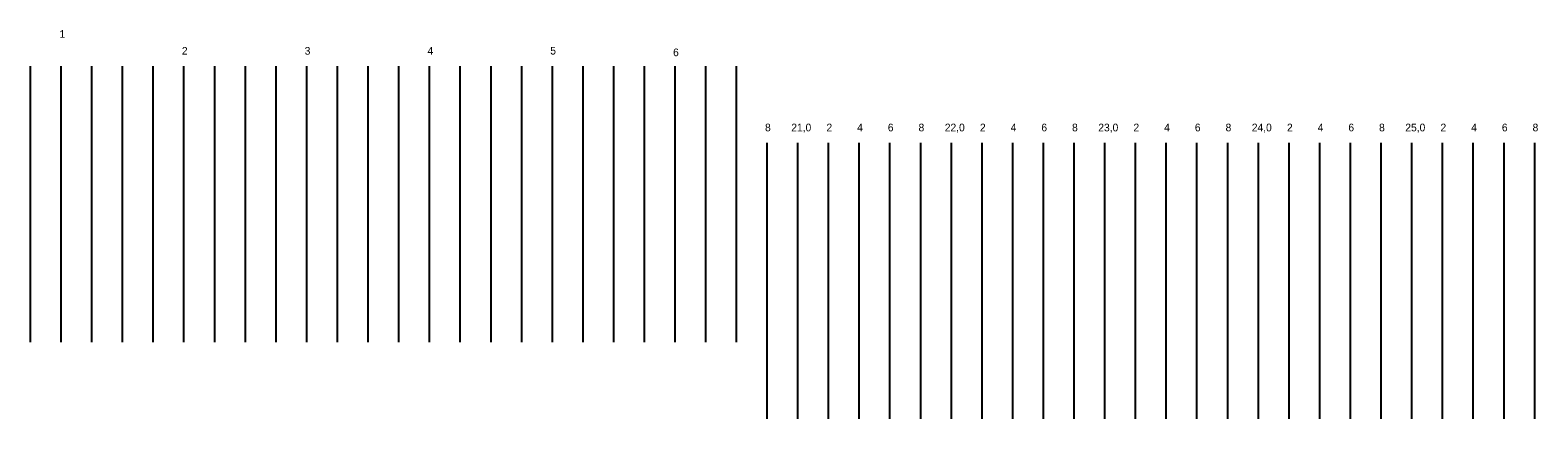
# Model space of a CAD drawing. Extents: x -1424 to 5155, y -2900 to 2050.
# Drawn here: x 1880 to 2862, y -1540 to -1286 of the extents above; entities that cross this region are included whole.
import ezdxf

# ---------------------------------------------------------------- set-up
doc = ezdxf.new("R2010")
doc.units = 0
doc.layers.add('NAVRHOVANÉ', color=7, linetype='Continuous')

msp = doc.modelspace()

# ---------------------------------------------------------------- linework, layer by layer
at = {"layer": 'NAVRHOVANÉ'}
for p, q in [((1880, -1310), (1880, -1490)), ((1900, -1310), (1900, -1490)), ((1920, -1310), (1920, -1490)), ((1940, -1310), (1940, -1490)), ((1960, -1310), (1960, -1490)), ((1980, -1310), (1980, -1490)), ((2000, -1310), (2000, -1490)), ((2020, -1310), (2020, -1490)), ((2040, -1310), (2040, -1490)), ((2060, -1310), (2060, -1490)), ((2080, -1310), (2080, -1490)), ((2100, -1310), (2100, -1490)), ((2100, -1310), (2100, -1490)), ((2120, -1310), (2120, -1490)), ((2140, -1310), (2140, -1490)), ((2160, -1310), (2160, -1490)), ((2180, -1310), (2180, -1490)), ((2200, -1310), (2200, -1490)), ((2220, -1310), (2220, -1490)), ((2240, -1310), (2240, -1490)), ((2260, -1310), (2260, -1490)), ((2280, -1310), (2280, -1490)), ((2300, -1310), (2300, -1490)), ((2320, -1310), (2320, -1490)), ((2340, -1310), (2340, -1490)), ((2359.9, -1360), (2359.9, -1540)), ((2379.9, -1360), (2379.9, -1540)), ((2399.9, -1360), (2399.9, -1540)), ((2419.9, -1360), (2419.9, -1540)), ((2439.9, -1360), (2439.9, -1540)), ((2459.9, -1360), (2459.9, -1540)), ((2479.9, -1360), (2479.9, -1540)), ((2499.9, -1360), (2499.9, -1540)), ((2519.9, -1360), (2519.9, -1540)), ((2539.9, -1360), (2539.9, -1540)), ((2559.9, -1360), (2559.9, -1540)), ((2579.9, -1360), (2579.9, -1540)), ((2599.9, -1360), (2599.9, -1540)), ((2619.9, -1360), (2619.9, -1540)), ((2639.9, -1360), (2639.9, -1540)), ((2659.9, -1360), (2659.9, -1540)), ((2679.9, -1360), (2679.9, -1540)), ((2699.9, -1360), (2699.9, -1540)), ((2719.9, -1360), (2719.9, -1540)), ((2739.9, -1360), (2739.9, -1540)), ((2759.9, -1360), (2759.9, -1540)), ((2779.9, -1360), (2779.9, -1540)), ((2799.9, -1360), (2799.9, -1540)), ((2819.9, -1360), (2819.9, -1540)), ((2839.9, -1360), (2839.9, -1540)), ((2859.9, -1360), (2859.9, -1540))]:
    msp.add_line(p, q, dxfattribs=at)

# ---------------------------------------------------------------- texts
for s, p in [('1', (1899.12, -1291.5)), ('2', (1978.85, -1302.5)), ('3', (2058.83, -1302.5)), ('4', (2138.84, -1302.48)), ('5', (2218.82, -1302.42)), ('6', (2298.83, -1303.5)), ('8', (2358.73, -1352.5)), ('21,0', (2375.82, -1352.5)), ('2', (2398.74, -1352.5)), ('4', (2418.74, -1352.48)), ('6', (2438.73, -1352.5)), ('8', (2458.73, -1352.5)), ('22,0', (2475.82, -1352.5)), ('2', (2498.74, -1352.5)), ('4', (2518.74, -1352.48)), ('6', (2538.73, -1352.5)), ('8', (2558.73, -1352.5)), ('23,0', (2575.82, -1352.5)), ('2', (2598.74, -1352.5)), ('4', (2618.74, -1352.48)), ('6', (2638.73, -1352.5)), ('8', (2658.73, -1352.5)), ('24,0', (2675.82, -1352.5)), ('2', (2698.74, -1352.5)), ('4', (2718.74, -1352.48)), ('6', (2738.73, -1352.5)), ('8', (2758.73, -1352.5)), ('25,0', (2775.82, -1352.5)), ('2', (2798.74, -1352.5)), ('4', (2818.74, -1352.48)), ('6', (2838.73, -1352.5)), ('8', (2858.73, -1352.5))]:
    msp.add_text(s, height=5).set_placement(p)

doc.saveas('drawing.dxf')
